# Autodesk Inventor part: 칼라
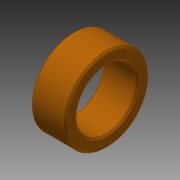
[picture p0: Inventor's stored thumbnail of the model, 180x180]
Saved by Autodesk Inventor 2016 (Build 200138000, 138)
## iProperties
Created: 2015-09
Part Number: 칼라
Material: 강철, 연강
Document SubType Name: Modeling
Designer: mduedu
Density: 7.86 g/cm^3
Description: 외주 가공
Mass: 17.8983 g
Surface Area: 15.6581 cm^2
Volume: 2.27713 cm^3
Appearance: 주황색
Author: mduedu
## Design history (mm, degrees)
sketch "스케치1"
  geometry: C1 r 12 at (0, 0); C2 r 8.5 at (0, 0); 1 further point
  constraints: 2 centre point, 2 coincident
  dimensions: "d0" = 24 diameter of C1; "d2" = 17 diameter of C2
extrude "돌출1" new body sketch "스케치1" distance "d3" = 10; taper "d4" = 0 deg
chamfer "모따기1" distance "d5" = 0.5; stored, may be unused: second distance "d6" = 2, angle "d7" = 45 deg
node "솔리드1"
